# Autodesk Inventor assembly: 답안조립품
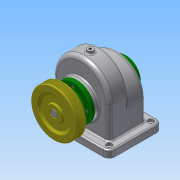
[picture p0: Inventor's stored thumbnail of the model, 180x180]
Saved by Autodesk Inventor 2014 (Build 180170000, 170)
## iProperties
Created: 2017-11
Part Number: 답안조립품
Document SubType Name: Assembly
Designer: sda
Author: sda
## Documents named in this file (14)
- C:\Users\sda\Desktop\471107V1034\답안조립품.iam
- C:\Users\sda\Desktop\471107V1034\본체.ipt
- C:\Users\sda\Desktop\471107V1034\V-벨트풀리.ipt
- C:\Users\sda\Desktop\471107V1034\뒤커버.ipt
- C:\Users\sda\Desktop\471107V1034\멈춤나사 - M4 x 10.ipt
- 멈춤나사 - M4 x 10.ipt
- C:\Users\sda\Desktop\471107V1034\베어링 6002.ipt
- C:\Users\sda\Desktop\471107V1034\볼트 M3 x 8.ipt
- C:\Users\sda\Desktop\471107V1034\스퍼기어.ipt
- C:\Users\sda\Desktop\471107V1034\앞커버.ipt
- C:\Users\sda\Desktop\471107V1034\오일 실 15 30 7.ipt
- C:\Users\sda\Desktop\471107V1034\축.ipt
- C:\Users\sda\Desktop\471107V1034\키 - 5 x 5 x 18.ipt
- C:\Users\sda\Desktop\471107V1034\키 - 6 x 6 x 22.ipt
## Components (1 placed, 1 different names)
1. V-벨트풀리:1
